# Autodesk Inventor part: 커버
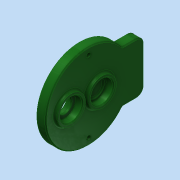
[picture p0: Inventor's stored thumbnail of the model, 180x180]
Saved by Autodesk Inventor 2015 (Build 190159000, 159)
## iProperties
Created: 2016-02
Part Number: 커버
Material: 알루미늄 6061
Document SubType Name: Modeling
Designer: mduedu
Density: 2.71 g/cm^3
Appearance: 매끄러움 - 짙은 산림 녹색
Mass: 157.248 g
Surface Area: 178.476 cm^2
Volume: 58.0252 cm^3
Author: mduedu
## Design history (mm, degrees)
sketch "스케치1"
  geometry: C1 r 43 at (0, 0); 1 further point
  constraints: 1 centre point, 1 coincident
  dimensions: "d0" = 86 diameter of C1
extrude "돌출1" new body sketch "스케치1" distance "d1" = 9; taper "d2" = 0 deg
sketch "스케치2"
  geometry: C1 r 14 at (0, 11); 1 further point
  constraints: 1 centre point, 1 vertical alignment
  dimensions: "d3" = 28 diameter of C1; "d6" = 11 distance of C1.centre point (0, 0)
extrude "돌출2" join sketch "스케치2" distance "d7" = 3; taper "d8" = 0 deg
sketch "스케치3"
  geometry: C1 r 14 at (0, -20); 1 further point
  constraints: 1 centre point, 1 vertical alignment
  dimensions: "d9" = 28 diameter of C1; "d10" = 20 distance of C1.centre point (0, 0)
extrude "돌출3" join sketch "스케치3" distance "d11" = 3; taper "d12" = 0 deg
hole "구멍1" diameter "d15" = 22; stored, may be unused: countersink angle "d19" = 90 deg, drill point angle "d21" = 0 deg; dims "d13" = 10, "d14" = 10, "d16" = 6, "d17" = 4, "d18" = 2, "d20" = 7
hole "구멍2" diameter "d24" = 18; stored, may be unused: countersink angle "d28" = 90 deg, drill point angle "d30" = 0 deg; dims "d22" = 10, "d23" = 10, "d25" = 6, "d26" = 4, "d27" = 2, "d29" = 1
hole "구멍3" diameter "d33" = 22; stored, may be unused: countersink angle "d37" = 90 deg, drill point angle "d39" = 0 deg; dims "d34" = 6, "d35" = 4, "d36" = 2, "d38" = 7, "d73" = 10, "d74" = 10
sketch "스케치7"
  geometry: L1 (-26, 34.249)-(26, 34.249); L2 (26, 34.249)-(26, 56); L3 (26, 56)-(-26, 56); L4 (-26, 56)-(-26, 34.249); A1 r 43 centre (0, 0) between (-26, 34.249) and (26, 34.249) reference; 1 further point
  constraints: 8 end point, 2 parallel, 2 point on circle, 1 horizontal, 1 perpendicular
  dimensions: "d95" = 52 distance of L2.end L3.end; "d97" = 56 distance from line of L3 point (0, 0)
extrude "돌출5" join sketch "스케치7" stored distance "d98" = 10; taper "d99" = 0 deg
sketch "스케치4"
  geometry: C1 r 14 at (0, -20) reference; C2 r 18 at (0, -20); 1 further point
  constraints: 1 centre point, 1 coincident
  dimensions: "d40" = 36 diameter of C2
extrude "돌출4" join sketch "스케치4" distance "d41" = 4; taper "d42" = 0 deg
hole "구멍4" diameter "d45" = 22; stored, may be unused: countersink angle "d49" = 90 deg, drill point angle "d51" = 0 deg; dims "d43" = 10, "d44" = 10, "d46" = 6, "d47" = 4, "d48" = 2, "d50" = 7
hole "구멍5" diameter "d54" = 15; stored, may be unused: countersink angle "d58" = 90 deg, drill point angle "d60" = 0 deg; dims "d52" = 10, "d53" = 10, "d55" = 6, "d56" = 4, "d57" = 2, "d59" = 7
fillet "모깎기1" dims "d61" = 0.3
fillet "모깎기2" dims "d62" = 2
chamfer "모따기1" distance "d63" = 1; stored, may be unused: second distance "d64" = 2, angle "d65" = 45 deg
fillet "모깎기6" dims "d88" = 2
sketch "스케치5" dims "d67" = 72
  geometry: 4 further points
  constraints: 2 horizontal alignment, 1 coincident, 5 other
  dimensions: "d71" = 360 deg dimension on point (0, 0) point (-36, 0) (derived)
fillet "모깎기4" dims "d75" = 2
sketch "스케치6"
  geometry: 2 further points
hole "구멍6" sketch "스케치6" at (36, 0), (-36, 0) diameter "d76" = 4.5; stored, may be unused: countersink angle "d80" = 90 deg, drill point angle "d82" = 0 deg; dims "d77" = 6, "d78" = 8, "d79" = 4.6, "d81" = 8
fillet "모깎기7" dims "d100" = 8, "d101" = 2
chamfer "모따기2" distance "d90" = 1; stored, may be unused: second distance "d91" = 2, angle "d92" = 45 deg
node "솔리드1"
node "절단 모서리 투영1"
